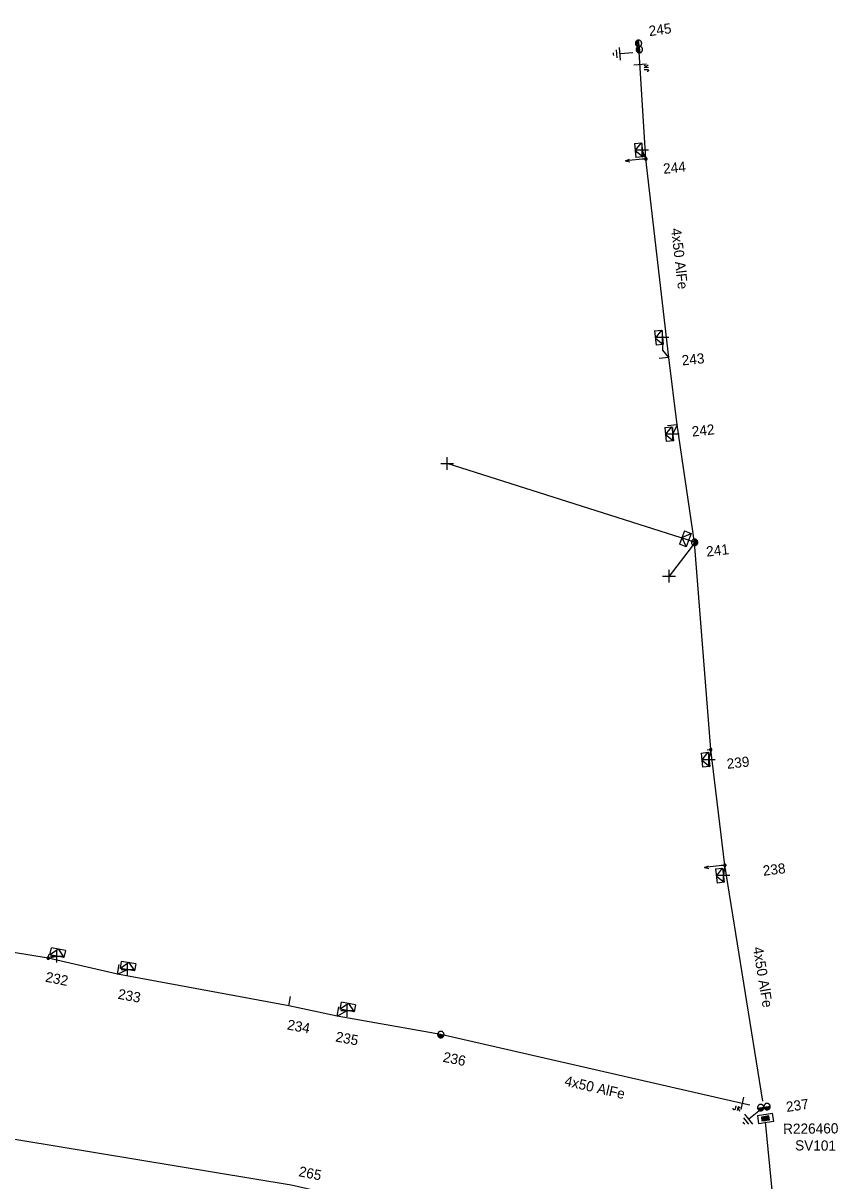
# Model space of a CAD drawing. Extents: x -544780 to -541582, y -1198995 to -1196551.
# Drawn here: x -542113.7 to -542033.7, y -1198657.1 to -1198543.5 of the extents above; entities that cross this region are included whole.
import ezdxf

# ---------------------------------------------------------------- set-up
doc = ezdxf.new("R2010")
doc.units = 0
for name, color, linetype in [('Vrstva 1', 7, 'Continuous'), ('Vrstva 13', 7, 'Continuous'), ('Vrstva 14', 7, 'Continuous'), ('Vrstva 15', 7, 'Continuous'), ('Vrstva 18', 7, 'Continuous'), ('Vrstva 2', 7, 'Continuous'), ('Vrstva 28', 7, 'Continuous'), ('Vrstva 29', 7, 'Continuous'), ('Vrstva 30', 7, 'Continuous'), ('Vrstva 31', 7, 'Continuous'), ('Vrstva 34', 7, 'Continuous'), ('Vrstva 54', 7, 'Continuous'), ('Vrstva 59', 7, 'Continuous'), ('Vrstva 8', 7, 'Continuous'), ('Vrstva 9', 7, 'Continuous')]:
    doc.layers.add(name, color=color, linetype=linetype)

# ---------------------------------------------------------------- blocks, each defined once
blk = doc.blocks.new('NN440')
at = {"layer": 'Vrstva 2'}
for points in [[(0.63, 0), (0.63, 0.06), (0.62, 0.13), (0.6, 0.19), (0.58, 0.25), (0.55, 0.31), (0.51, 0.37), (0.47, 0.42), (0.42, 0.46), (0.37, 0.51), (0.32, 0.54), (0.26, 0.57), (0.2, 0.59), (0.13, 0.61), (0.07, 0.62), (0, 0.63), (-0.06, 0.62), (-0.13, 0.61), (-0.19, 0.59), (-0.26, 0.57), (-0.31, 0.54), (-0.37, 0.51), (-0.42, 0.46), (-0.47, 0.42), (-0.51, 0.37), (-0.54, 0.31), (-0.57, 0.25), (-0.6, 0.19), (-0.62, 0.13), (-0.63, 0.06), (-0.63, 0), (-0.63, -0.07), (-0.62, -0.14), (-0.6, -0.2), (-0.57, -0.26), (-0.54, -0.32), (-0.51, -0.37), (-0.47, -0.43), (-0.42, -0.47), (-0.37, -0.51), (-0.31, -0.55), (-0.26, -0.58), (-0.19, -0.6), (-0.13, -0.62), (-0.06, -0.63), (0, -0.63), (0.07, -0.63), (0.13, -0.62), (0.2, -0.6), (0.26, -0.58), (0.32, -0.55), (0.37, -0.51), (0.42, -0.47), (0.47, -0.43), (0.51, -0.37), (0.55, -0.32), (0.58, -0.26), (0.6, -0.2), (0.62, -0.14), (0.63, -0.07), (0.63, 0)], [(-0.63, 0), (0.63, 0)], [(-0.6, -0.18), (0.57, -0.18)], [(-0.51, -0.32), (0.5, -0.32)], [(-0.37, -0.47), (0.35, -0.47)]]:
    blk.add_lwpolyline(points, dxfattribs=at)
blk = doc.blocks.new('NN450')
at = {"layer": 'Vrstva 2'}
for points in [[(0, 0), (0, 0.07), (-0.01, 0.13), (-0.03, 0.19), (-0.05, 0.25), (-0.08, 0.31), (-0.12, 0.37), (-0.16, 0.42), (-0.21, 0.46), (-0.26, 0.51), (-0.31, 0.54), (-0.37, 0.57), (-0.43, 0.59), (-0.5, 0.61), (-0.56, 0.62), (-0.63, 0.62), (-0.69, 0.62), (-0.75, 0.61), (-0.82, 0.59), (-0.88, 0.57), (-0.94, 0.54), (-0.99, 0.51), (-1.04, 0.46), (-1.09, 0.42), (-1.13, 0.37), (-1.17, 0.31), (-1.2, 0.25), (-1.22, 0.19), (-1.24, 0.13), (-1.25, 0.07), (-1.25, 0), (-1.25, -0.07), (-1.24, -0.13), (-1.22, -0.19), (-1.2, -0.25), (-1.17, -0.31), (-1.13, -0.37), (-1.09, -0.42), (-1.04, -0.46), (-0.99, -0.51), (-0.94, -0.54), (-0.88, -0.57), (-0.82, -0.59), (-0.75, -0.61), (-0.69, -0.62), (-0.62, -0.63), (-0.56, -0.62), (-0.5, -0.61), (-0.43, -0.59), (-0.37, -0.57), (-0.31, -0.54), (-0.26, -0.51), (-0.21, -0.46), (-0.16, -0.42), (-0.12, -0.37), (-0.08, -0.31), (-0.05, -0.25), (-0.03, -0.19), (-0.01, -0.13), (0, -0.07), (0, 0)], [(1.25, 0), (1.25, 0.07), (1.24, 0.13), (1.22, 0.19), (1.2, 0.25), (1.17, 0.31), (1.13, 0.37), (1.09, 0.42), (1.04, 0.46), (0.99, 0.51), (0.94, 0.54), (0.88, 0.57), (0.82, 0.59), (0.75, 0.61), (0.69, 0.62), (0.62, 0.62), (0.56, 0.62), (0.5, 0.61), (0.43, 0.59), (0.37, 0.57), (0.31, 0.54), (0.26, 0.51), (0.21, 0.46), (0.16, 0.42), (0.12, 0.37), (0.08, 0.31), (0.05, 0.25), (0.03, 0.19), (0.01, 0.13), (0, 0.07), (0, 0), (0, -0.07), (0.01, -0.13), (0.03, -0.19), (0.05, -0.25), (0.08, -0.31), (0.12, -0.37), (0.16, -0.42), (0.21, -0.46), (0.26, -0.51), (0.31, -0.54), (0.37, -0.57), (0.43, -0.59), (0.5, -0.61), (0.56, -0.62), (0.63, -0.63), (0.69, -0.62), (0.75, -0.61), (0.82, -0.59), (0.88, -0.57), (0.94, -0.54), (0.99, -0.51), (1.04, -0.46), (1.09, -0.42), (1.13, -0.37), (1.17, -0.31), (1.2, -0.25), (1.22, -0.19), (1.24, -0.13), (1.25, -0.07), (1.25, 0)], [(-1.25, 0), (1.25, 0)], [(-1.23, -0.16), (-0.02, -0.16)], [(-1.16, -0.32), (-0.09, -0.32)], [(-1.03, -0.47), (-0.22, -0.47)], [(0.02, -0.16), (1.23, -0.16)], [(0.09, -0.32), (1.16, -0.32)], [(0.22, -0.47), (1.03, -0.47)]]:
    blk.add_lwpolyline(points, dxfattribs=at)
blk = doc.blocks.new('NN560')
at = {"layer": 'Vrstva 2'}
for points in [[(2, 0), (1.59, 0.14)], [(0, 0), (2, 0)], [(2, 0), (1.59, -0.13)]]:
    blk.add_lwpolyline(points, dxfattribs=at)
blk = doc.blocks.new('NN840')
at = {"layer": 'Vrstva 15'}
for points in [[(0, 0.62), (0, -0.63)], [(-0.75, -0.71), (-0.75, -0.66)], [(-0.73, -0.76), (-0.75, -0.71)], [(-0.66, -0.8), (-0.73, -0.76)], [(-0.63, -0.8), (-0.66, -0.8)], [(-0.56, -0.76), (-0.63, -0.8)], [(-0.54, -0.71), (-0.56, -0.76)], [(-0.54, -0.38), (-0.54, -0.71)], [(-0.33, -0.38), (-0.33, -0.8)], [(-0.33, -0.64), (-0.13, -0.38)], [(-0.26, -0.56), (-0.09, -0.8)]]:
    blk.add_lwpolyline(points, dxfattribs=at)
blk = doc.blocks.new('NN800')
at = {"layer": 'Vrstva 1'}
for points in [[(-0.44, 0.44), (0.44, -0.44)], [(-0.44, -0.44), (0.44, 0.44)]]:
    blk.add_lwpolyline(points, dxfattribs=at)
blk = doc.blocks.new('NN620')
at = {"layer": 'Vrstva 8'}
for points in [[(0.75, 0), (-0.75, 0)], [(-0.75, 0), (-0.75, -0.75)], [(0.75, -0.75), (0.75, 0)], [(-0.75, -0.75), (0.75, -0.75)], [(0.37, -0.18), (-0.38, -0.18)], [(-0.38, -0.18), (-0.38, -0.56)], [(-0.38, -0.56), (0.37, -0.56)], [(0.32, -0.23), (-0.33, -0.23)], [(-0.33, -0.23), (-0.33, -0.51)], [(-0.33, -0.51), (0.32, -0.51)], [(0.27, -0.27), (-0.28, -0.27)], [(-0.28, -0.27), (-0.28, -0.46)], [(-0.28, -0.46), (0.27, -0.46)], [(0.23, -0.32), (-0.23, -0.32)], [(-0.23, -0.32), (-0.23, -0.42)], [(-0.23, -0.42), (0.23, -0.42)], [(-0.19, -0.37), (0.19, -0.37)], [(0.23, -0.42), (0.23, -0.32)], [(0.27, -0.46), (0.27, -0.27)], [(0.32, -0.51), (0.32, -0.23)], [(0.37, -0.56), (0.37, -0.18)]]:
    blk.add_lwpolyline(points, dxfattribs=at)
blk = doc.blocks.new('NN630')
at = {"layer": 'Vrstva 9'}
for points in [[(0, -0.7), (-0.7, 0)], [(-0.7, -0.7), (-0.7, 0), (0.7, 0), (0.7, -0.7)], [(-0.7, -0.7), (0.7, -0.7)], [(0, -0.7), (0.7, 0)]]:
    blk.add_lwpolyline(points, dxfattribs=at)
blk = doc.blocks.new('NN810')
at = {"layer": 'Vrstva 14'}
for points in [[(0, -0.64), (0, -1.89)], [(0.63, -1.89), (-0.62, -1.89)], [(0.39, -2.2), (-0.4, -2.2)], [(0, -2.52), (-0.12, -2.52)], [(0.14, -2.52), (0, -2.52)]]:
    blk.add_lwpolyline(points, dxfattribs=at)
blk = doc.blocks.new('NN500')
at = {"layer": 'Vrstva 2'}
for points in [[(0, -0.24), (0.02, -0.23), (0.05, -0.23), (0.07, -0.22), (0.09, -0.22), (0.12, -0.2), (0.14, -0.19), (0.16, -0.18), (0.17, -0.16), (0.19, -0.14), (0.2, -0.12), (0.21, -0.1), (0.22, -0.07), (0.23, -0.05), (0.23, -0.02), (0.23, 0), (0.23, 0.02), (0.23, 0.05), (0.22, 0.07), (0.21, 0.1), (0.2, 0.12), (0.19, 0.14), (0.17, 0.16), (0.16, 0.17), (0.14, 0.19), (0.12, 0.2), (0.09, 0.21), (0.07, 0.22), (0.05, 0.23), (0.02, 0.23), (0, 0.23), (-0.03, 0.23), (-0.05, 0.23), (-0.07, 0.22), (-0.1, 0.21), (-0.12, 0.2), (-0.14, 0.19), (-0.16, 0.17), (-0.18, 0.16), (-0.19, 0.14), (-0.2, 0.12), (-0.22, 0.1), (-0.22, 0.07), (-0.23, 0.05), (-0.23, 0.02), (-0.24, 0), (-0.23, -0.02), (-0.23, -0.05), (-0.22, -0.07), (-0.22, -0.1), (-0.2, -0.12), (-0.19, -0.14), (-0.18, -0.16), (-0.16, -0.18), (-0.14, -0.19), (-0.12, -0.2), (-0.1, -0.22), (-0.07, -0.22), (-0.05, -0.23), (-0.03, -0.23), (0, -0.24)], [(0, -0.24), (0.02, -0.23), (0.05, -0.23), (0.07, -0.22), (0.09, -0.22), (0.12, -0.2), (0.14, -0.19), (0.16, -0.18), (0.17, -0.16), (0.19, -0.14), (0.2, -0.12), (0.21, -0.1), (0.22, -0.07), (0.23, -0.05), (0.23, -0.02), (0.23, 0), (0.23, 0.02), (0.23, 0.05), (0.22, 0.07), (0.21, 0.1), (0.2, 0.12), (0.19, 0.14), (0.17, 0.16), (0.16, 0.17), (0.14, 0.19), (0.12, 0.2), (0.09, 0.21), (0.07, 0.22), (0.05, 0.23), (0.02, 0.23), (0, 0.23), (-0.03, 0.23), (-0.05, 0.23), (-0.07, 0.22), (-0.1, 0.21), (-0.12, 0.2), (-0.14, 0.19), (-0.16, 0.17), (-0.18, 0.16), (-0.19, 0.14), (-0.2, 0.12), (-0.22, 0.1), (-0.22, 0.07), (-0.23, 0.05), (-0.23, 0.02), (-0.24, 0), (-0.23, -0.02), (-0.23, -0.05), (-0.22, -0.07), (-0.22, -0.1), (-0.2, -0.12), (-0.19, -0.14), (-0.18, -0.16), (-0.16, -0.18), (-0.14, -0.19), (-0.12, -0.2), (-0.1, -0.22), (-0.07, -0.22), (-0.05, -0.23), (-0.03, -0.23), (0, -0.24)], [(0, -0.21), (0.02, -0.2), (0.04, -0.2), (0.06, -0.2), (0.08, -0.19), (0.1, -0.18), (0.12, -0.17), (0.14, -0.15), (0.15, -0.14), (0.16, -0.12), (0.18, -0.1), (0.19, -0.08), (0.19, -0.06), (0.2, -0.04), (0.2, -0.02), (0.2, 0), (0.2, 0.02), (0.2, 0.04), (0.19, 0.06), (0.19, 0.08), (0.18, 0.1), (0.16, 0.12), (0.15, 0.14), (0.14, 0.15), (0.12, 0.17), (0.1, 0.18), (0.08, 0.19), (0.06, 0.19), (0.04, 0.2), (0.02, 0.2), (0, 0.2), (-0.02, 0.2), (-0.04, 0.2), (-0.06, 0.19), (-0.08, 0.19), (-0.1, 0.18), (-0.12, 0.17), (-0.14, 0.15), (-0.15, 0.14), (-0.17, 0.12), (-0.18, 0.1), (-0.19, 0.08), (-0.2, 0.06), (-0.2, 0.04), (-0.21, 0.02), (-0.21, 0), (-0.21, -0.02), (-0.2, -0.04), (-0.2, -0.06), (-0.19, -0.08), (-0.18, -0.1), (-0.17, -0.12), (-0.15, -0.14), (-0.14, -0.15), (-0.12, -0.17), (-0.1, -0.18), (-0.08, -0.19), (-0.06, -0.2), (-0.04, -0.2), (-0.02, -0.2), (0, -0.21)], [(0, -0.18), (0.02, -0.18), (0.04, -0.17), (0.05, -0.17), (0.07, -0.16), (0.09, -0.15), (0.1, -0.14), (0.12, -0.13), (0.13, -0.12), (0.14, -0.1), (0.15, -0.09), (0.16, -0.07), (0.17, -0.05), (0.17, -0.04), (0.17, -0.02), (0.17, 0), (0.17, 0.02), (0.17, 0.04), (0.17, 0.05), (0.16, 0.07), (0.15, 0.09), (0.14, 0.1), (0.13, 0.12), (0.12, 0.13), (0.1, 0.14), (0.09, 0.15), (0.07, 0.16), (0.05, 0.17), (0.04, 0.17), (0.02, 0.17), (0, 0.18), (-0.02, 0.17), (-0.04, 0.17), (-0.06, 0.17), (-0.07, 0.16), (-0.09, 0.15), (-0.1, 0.14), (-0.12, 0.13), (-0.13, 0.12), (-0.14, 0.1), (-0.15, 0.09), (-0.16, 0.07), (-0.17, 0.05), (-0.17, 0.04), (-0.18, 0.02), (-0.18, 0), (-0.18, -0.02), (-0.17, -0.04), (-0.17, -0.05), (-0.16, -0.07), (-0.15, -0.09), (-0.14, -0.1), (-0.13, -0.12), (-0.12, -0.13), (-0.1, -0.14), (-0.09, -0.15), (-0.07, -0.16), (-0.06, -0.17), (-0.04, -0.17), (-0.02, -0.18), (0, -0.18)], [(0, -0.15), (0.01, -0.15), (0.03, -0.14), (0.04, -0.14), (0.06, -0.13), (0.07, -0.13), (0.08, -0.12), (0.1, -0.11), (0.11, -0.1), (0.12, -0.09), (0.13, -0.07), (0.13, -0.06), (0.14, -0.05), (0.14, -0.03), (0.14, -0.02), (0.14, 0), (0.14, 0.01), (0.14, 0.03), (0.14, 0.04), (0.13, 0.06), (0.13, 0.07), (0.12, 0.09), (0.11, 0.1), (0.1, 0.11), (0.08, 0.12), (0.07, 0.13), (0.06, 0.13), (0.04, 0.14), (0.03, 0.14), (0.01, 0.14), (0, 0.15), (-0.02, 0.14), (-0.03, 0.14), (-0.05, 0.14), (-0.06, 0.13), (-0.07, 0.13), (-0.09, 0.12), (-0.1, 0.11), (-0.11, 0.1), (-0.12, 0.09), (-0.13, 0.07), (-0.13, 0.06), (-0.14, 0.04), (-0.14, 0.03), (-0.15, 0.01), (-0.15, 0), (-0.15, -0.02), (-0.14, -0.03), (-0.14, -0.05), (-0.13, -0.06), (-0.13, -0.07), (-0.12, -0.09), (-0.11, -0.1), (-0.1, -0.11), (-0.09, -0.12), (-0.07, -0.13), (-0.06, -0.13), (-0.05, -0.14), (-0.03, -0.14), (-0.02, -0.15), (0, -0.15)], [(0, -0.12), (0.01, -0.12), (0.02, -0.11), (0.03, -0.11), (0.05, -0.11), (0.06, -0.1), (0.07, -0.09), (0.08, -0.09), (0.09, -0.08), (0.09, -0.07), (0.1, -0.06), (0.11, -0.05), (0.11, -0.04), (0.11, -0.02), (0.11, -0.01), (0.12, 0), (0.11, 0.01), (0.11, 0.02), (0.11, 0.04), (0.11, 0.05), (0.1, 0.06), (0.09, 0.07), (0.09, 0.08), (0.08, 0.09), (0.07, 0.09), (0.06, 0.1), (0.05, 0.11), (0.03, 0.11), (0.02, 0.11), (0.01, 0.12), (0, 0.12), (-0.01, 0.12), (-0.03, 0.11), (-0.04, 0.11), (-0.05, 0.11), (-0.06, 0.1), (-0.07, 0.09), (-0.08, 0.09), (-0.09, 0.08), (-0.1, 0.07), (-0.1, 0.06), (-0.11, 0.05), (-0.11, 0.04), (-0.12, 0.02), (-0.12, 0.01), (-0.12, 0), (-0.12, -0.01), (-0.12, -0.02), (-0.11, -0.04), (-0.11, -0.05), (-0.1, -0.06), (-0.1, -0.07), (-0.09, -0.08), (-0.08, -0.09), (-0.07, -0.09), (-0.06, -0.1), (-0.05, -0.11), (-0.04, -0.11), (-0.03, -0.11), (-0.01, -0.12), (0, -0.12)], [(0, -0.09), (0.01, -0.09), (0.02, -0.09), (0.03, -0.08), (0.03, -0.08), (0.04, -0.08), (0.05, -0.07), (0.06, -0.07), (0.06, -0.06), (0.07, -0.05), (0.07, -0.04), (0.08, -0.04), (0.08, -0.03), (0.08, -0.02), (0.09, -0.01), (0.09, 0), (0.09, 0.01), (0.08, 0.02), (0.08, 0.03), (0.08, 0.03), (0.07, 0.04), (0.07, 0.05), (0.06, 0.06), (0.06, 0.06), (0.05, 0.07), (0.04, 0.07), (0.03, 0.08), (0.03, 0.08), (0.02, 0.08), (0.01, 0.09), (0, 0.09), (-0.01, 0.09), (-0.02, 0.08), (-0.03, 0.08), (-0.04, 0.08), (-0.04, 0.07), (-0.05, 0.07), (-0.06, 0.06), (-0.07, 0.06), (-0.07, 0.05), (-0.08, 0.04), (-0.08, 0.03), (-0.08, 0.03), (-0.09, 0.02), (-0.09, 0.01), (-0.09, 0), (-0.09, -0.01), (-0.09, -0.02), (-0.08, -0.03), (-0.08, -0.04), (-0.08, -0.04), (-0.07, -0.05), (-0.07, -0.06), (-0.06, -0.07), (-0.05, -0.07), (-0.04, -0.08), (-0.04, -0.08), (-0.03, -0.08), (-0.02, -0.09), (-0.01, -0.09), (0, -0.09)], [(0, -0.06), (0, -0.06), (0.01, -0.06), (0.02, -0.05), (0.02, -0.05), (0.03, -0.05), (0.03, -0.05), (0.04, -0.04), (0.04, -0.04), (0.05, -0.03), (0.05, -0.03), (0.05, -0.02), (0.05, -0.02), (0.05, -0.01), (0.06, -0.01), (0.06, 0), (0.06, 0.01), (0.05, 0.01), (0.05, 0.02), (0.05, 0.02), (0.05, 0.03), (0.05, 0.03), (0.04, 0.04), (0.04, 0.04), (0.03, 0.05), (0.03, 0.05), (0.02, 0.05), (0.02, 0.05), (0.01, 0.06), (0, 0.06), (0, 0.06), (-0.01, 0.06), (-0.01, 0.06), (-0.02, 0.05), (-0.02, 0.05), (-0.03, 0.05), (-0.03, 0.05), (-0.04, 0.04), (-0.04, 0.04), (-0.05, 0.03), (-0.05, 0.03), (-0.05, 0.02), (-0.06, 0.02), (-0.06, 0.01), (-0.06, 0.01), (-0.06, 0), (-0.06, -0.01), (-0.06, -0.01), (-0.06, -0.02), (-0.05, -0.02), (-0.05, -0.03), (-0.05, -0.03), (-0.04, -0.04), (-0.04, -0.04), (-0.03, -0.05), (-0.03, -0.05), (-0.02, -0.05), (-0.02, -0.05), (-0.01, -0.06), (-0.01, -0.06), (0, -0.06)], [(0, -0.03), (0, -0.03), (0, -0.03), (0.01, -0.03), (0.01, -0.03), (0.01, -0.02), (0.02, -0.02), (0.02, -0.02), (0.02, -0.02), (0.02, -0.02), (0.02, -0.01), (0.02, -0.01), (0.03, -0.01), (0.03, -0.01), (0.03, 0), (0.03, 0), (0.03, 0), (0.03, 0.01), (0.03, 0.01), (0.02, 0.01), (0.02, 0.01), (0.02, 0.02), (0.02, 0.02), (0.02, 0.02), (0.02, 0.02), (0.01, 0.02), (0.01, 0.02), (0.01, 0.03), (0, 0.03), (0, 0.03), (0, 0.03), (0, 0.03), (-0.01, 0.03), (-0.01, 0.03), (-0.01, 0.02), (-0.02, 0.02), (-0.02, 0.02), (-0.02, 0.02), (-0.02, 0.02), (-0.02, 0.02), (-0.03, 0.01), (-0.03, 0.01), (-0.03, 0.01), (-0.03, 0.01), (-0.03, 0), (-0.03, 0), (-0.03, 0), (-0.03, -0.01), (-0.03, -0.01), (-0.03, -0.01), (-0.03, -0.01), (-0.02, -0.02), (-0.02, -0.02), (-0.02, -0.02), (-0.02, -0.02), (-0.02, -0.02), (-0.01, -0.03), (-0.01, -0.03), (-0.01, -0.03), (0, -0.03), (0, -0.03)], [(0.23, 0), (0.7, 0)]]:
    blk.add_lwpolyline(points, dxfattribs=at)
blk = doc.blocks.new('NN510')
at = {"layer": 'Vrstva 2'}
blk.add_lwpolyline([(0, 0), (0, 0.94)], dxfattribs=at)

msp = doc.modelspace()

# ---------------------------------------------------------------- linework, layer by layer
at = {"layer": 'Vrstva 1'}
for points in [[(-542041.1, -1198649.3), (-542044.83, -1198626.16), (-542046.21, -1198614.82), (-542047.8, -1198594.48), (-542049.52, -1198582.94), (-542050.33, -1198576.32), (-542052.58, -1198556.85), (-542053.26, -1198545.81)], [(-542039.71, -1198675.3), (-542040.53, -1198674.87), (-542063.64, -1198662.97), (-542087.39, -1198657.56), (-542117.71, -1198652.57), (-542142.48, -1198650.32), (-542153.84, -1198648.51), (-542165.61, -1198646.39), (-542176.66, -1198644.65), (-542189.96, -1198642.15), (-542195.05, -1198641.46), (-542204.23, -1198639.77), (-542208.42, -1198639.08), (-542219.22, -1198637.21), (-542230.02, -1198635.4), (-542250.83, -1198631.96), (-542269.04, -1198628.6), (-542276.53, -1198627.1), (-542287.9, -1198625.6), (-542301.67, -1198622.79), (-542314.54, -1198620.61), (-542337.89, -1198613.42)], [(-542042.39, -1198649.71), (-542043.13, -1198649.53), (-542072.7, -1198642.78), (-542082.88, -1198640.97), (-542087.62, -1198639.97), (-542104.42, -1198636.84), (-542111.23, -1198635.28), (-542122.88, -1198633.37)], [(-542038.52, -1198675.11), (-542040.85, -1198651.35)]]:
    msp.add_lwpolyline(points, dxfattribs=at)
at = {"layer": 'Vrstva 54'}
for points in [[(-542052.58, -1198556.85), (-542052.93, -1198555.95)], [(-542050.33, -1198576.32), (-542050.9, -1198575.61), (-542050.95, -1198574.35)], [(-542049.52, -1198582.94), (-542049.95, -1198583.82)], [(-542047.8, -1198594.48), (-542048.39, -1198594.26)], [(-542047.8, -1198594.48), (-542048.14, -1198594.97)], [(-542046.21, -1198614.82), (-542046.39, -1198615.77)], [(-542044.83, -1198626.16), (-542044.97, -1198627.14)], [(-542111.23, -1198635.28), (-542110.37, -1198635.08)], [(-542104.42, -1198636.84), (-542103.46, -1198636.41)], [(-542082.88, -1198640.97), (-542081.89, -1198640.41)]]:
    msp.add_lwpolyline(points, dxfattribs=at)
at = {"layer": 'Vrstva 59'}
for points in [[(-542048.39, -1198594.26), (-542072.07, -1198586.74)], [(-542048.14, -1198594.97), (-542050.31, -1198597.78)]]:
    msp.add_lwpolyline(points, dxfattribs=at)

# ---------------------------------------------------------------- block references
at = {"layer": 'Vrstva 13'}
for name, p, xscale, yscale, rotation in [('NN450', (-542053.26, -1198545.81), 0.5000000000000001, 0.5, -82.37401392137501), ('NN500', (-542052.58, -1198556.85), 0.49999999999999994, 0.5, -174.24899991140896), ('NN440', (-542047.8, -1198594.48), 0.5, 0.5, 96.4672583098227), ('NN500', (-542046.21, -1198614.82), 0.5000000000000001, 0.5, -173.74999998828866), ('NN500', (-542044.83, -1198626.16), 0.49999999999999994, 0.5000000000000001, -173.10600007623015), ('NN500', (-542111.23, -1198635.28), 0.5, 0.5000000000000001, 78.73500002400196), ('NN440', (-542072.7, -1198642.78), 0.49999999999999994, 0.5000000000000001, -11.325150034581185), ('NN450', (-542041, -1198649.9), 0.5, 0.4999999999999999, 8.969024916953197)]:
    msp.add_blockref(name, p, dxfattribs=dict(at, xscale=xscale, yscale=yscale, rotation=rotation))
for name, p, rotation in [('NN560', (-542052.58, -1198556.85), -174.24859722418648), ('NN510', (-542050.33, -1198576.32), 95.9740888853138), ('NN510', (-542049.51, -1198582.94), 95.97408895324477), ('NN560', (-542044.83, -1198626.16), -173.10573051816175), ('NN510', (-542104.42, -1198636.84), -10.378902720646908), ('NN510', (-542087.62, -1198639.97), -10.619655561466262), ('NN510', (-542082.88, -1198640.97), -10.619655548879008)]:
    msp.add_blockref(name, p, dxfattribs=dict(at, rotation=rotation))
at = {"layer": 'Vrstva 15'}
for p, rotation in [((-542053.23, -1198546.41), -86.44078335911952), ((-542041, -1198649.9), -51.409661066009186)]:
    msp.add_blockref('NN810', p, dxfattribs=dict(at, rotation=rotation))
at = {"layer": 'Vrstva 18'}
for p, rotation in [((-542053.15, -1198547.56), 93.55921671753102), ((-542043.13, -1198649.53), -12.869958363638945)]:
    msp.add_blockref('NN840', p, dxfattribs=dict(at, rotation=rotation))
at = {"layer": 'Vrstva 28', "rotation": 8.37199996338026}
msp.add_blockref('NN620', (-542040.89, -1198650.64), dxfattribs=at)
at = {"layer": 'Vrstva 31'}
for p, rotation in [((-542052.93, -1198555.95), -84.2485972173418), ((-542050.95, -1198574.35), -83.5207026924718), ((-542049.95, -1198583.82), -84.02591111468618), ((-542048.39, -1198594.26), -110.63088612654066), ((-542046.39, -1198615.77), -83.74988889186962), ((-542044.97, -1198627.14), -83.10573057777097), ((-542110.37, -1198635.08), 168.73532492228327), ((-542103.46, -1198636.41), 169.62109714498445), ((-542081.89, -1198640.41), 169.38034443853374)]:
    msp.add_blockref('NN630', p, dxfattribs=dict(at, rotation=rotation))
at = {"layer": 'Vrstva 34'}
for p, rotation in [((-542052.93, -1198555.95), 45), ((-542050.95, -1198574.35), 44.99999995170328), ((-542049.95, -1198583.82), 45), ((-542072.07, -1198586.74), 45.00000009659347), ((-542050.31, -1198597.78), 45), ((-542046.39, -1198615.77), 45), ((-542044.97, -1198627.14), 45), ((-542110.37, -1198635.08), 45), ((-542103.46, -1198636.41), 45), ((-542081.89, -1198640.41), 45)]:
    msp.add_blockref('NN800', p, dxfattribs=dict(at, rotation=rotation))

# ---------------------------------------------------------------- texts
at = {"layer": 'Vrstva 14'}
for s, rotation, p in [('245', 7.626, (-542052.23, -1198544.8)), ('244', 5.751, (-542050.84, -1198558.31)), ('243', 5.974, (-542049.01, -1198577.12)), ('242', 5.974, (-542048.02, -1198584.1)), ('241', 6.467, (-542046.6, -1198595.88)), ('239', 6.25, (-542044.59, -1198616.71)), ('238', 6.894, (-542041.04, -1198627.2)), ('232', 348.735, (-542111.57, -1198637.58)), ('233', 349.621, (-542104.45, -1198639.26)), ('234', 349.38, (-542087.84, -1198642.27)), ('235', 349.38, (-542083.09, -1198643.45)), ('236', 348.675, (-542072.56, -1198645.44)), ('237', 8.094, (-542038.75, -1198650.38)), ('265', 348.709, (-542086.71, -1198656.67))]:
    msp.add_text(s, height=1, rotation=rotation, dxfattribs=at).set_placement(p)
at = {"layer": 'Vrstva 2'}
for rotation, p in [(276.587, (-542050.11, -1198563.7)), (279.419, (-542042.08, -1198634.25)), (347.13, (-542060.63, -1198647.78))]:
    msp.add_text('4x50 AlFe', height=1, rotation=rotation, dxfattribs=at).set_placement(p)
at = {"layer": 'Vrstva 29'}
msp.add_text('R226460', height=1, rotation=0.566, dxfattribs=at).set_placement((-542039.11, -1198652.53))
at = {"layer": 'Vrstva 30'}
msp.add_text('SV101', height=1, rotation=359.588, dxfattribs=at).set_placement((-542037.94, -1198654.15))

doc.saveas('drawing.dxf')
